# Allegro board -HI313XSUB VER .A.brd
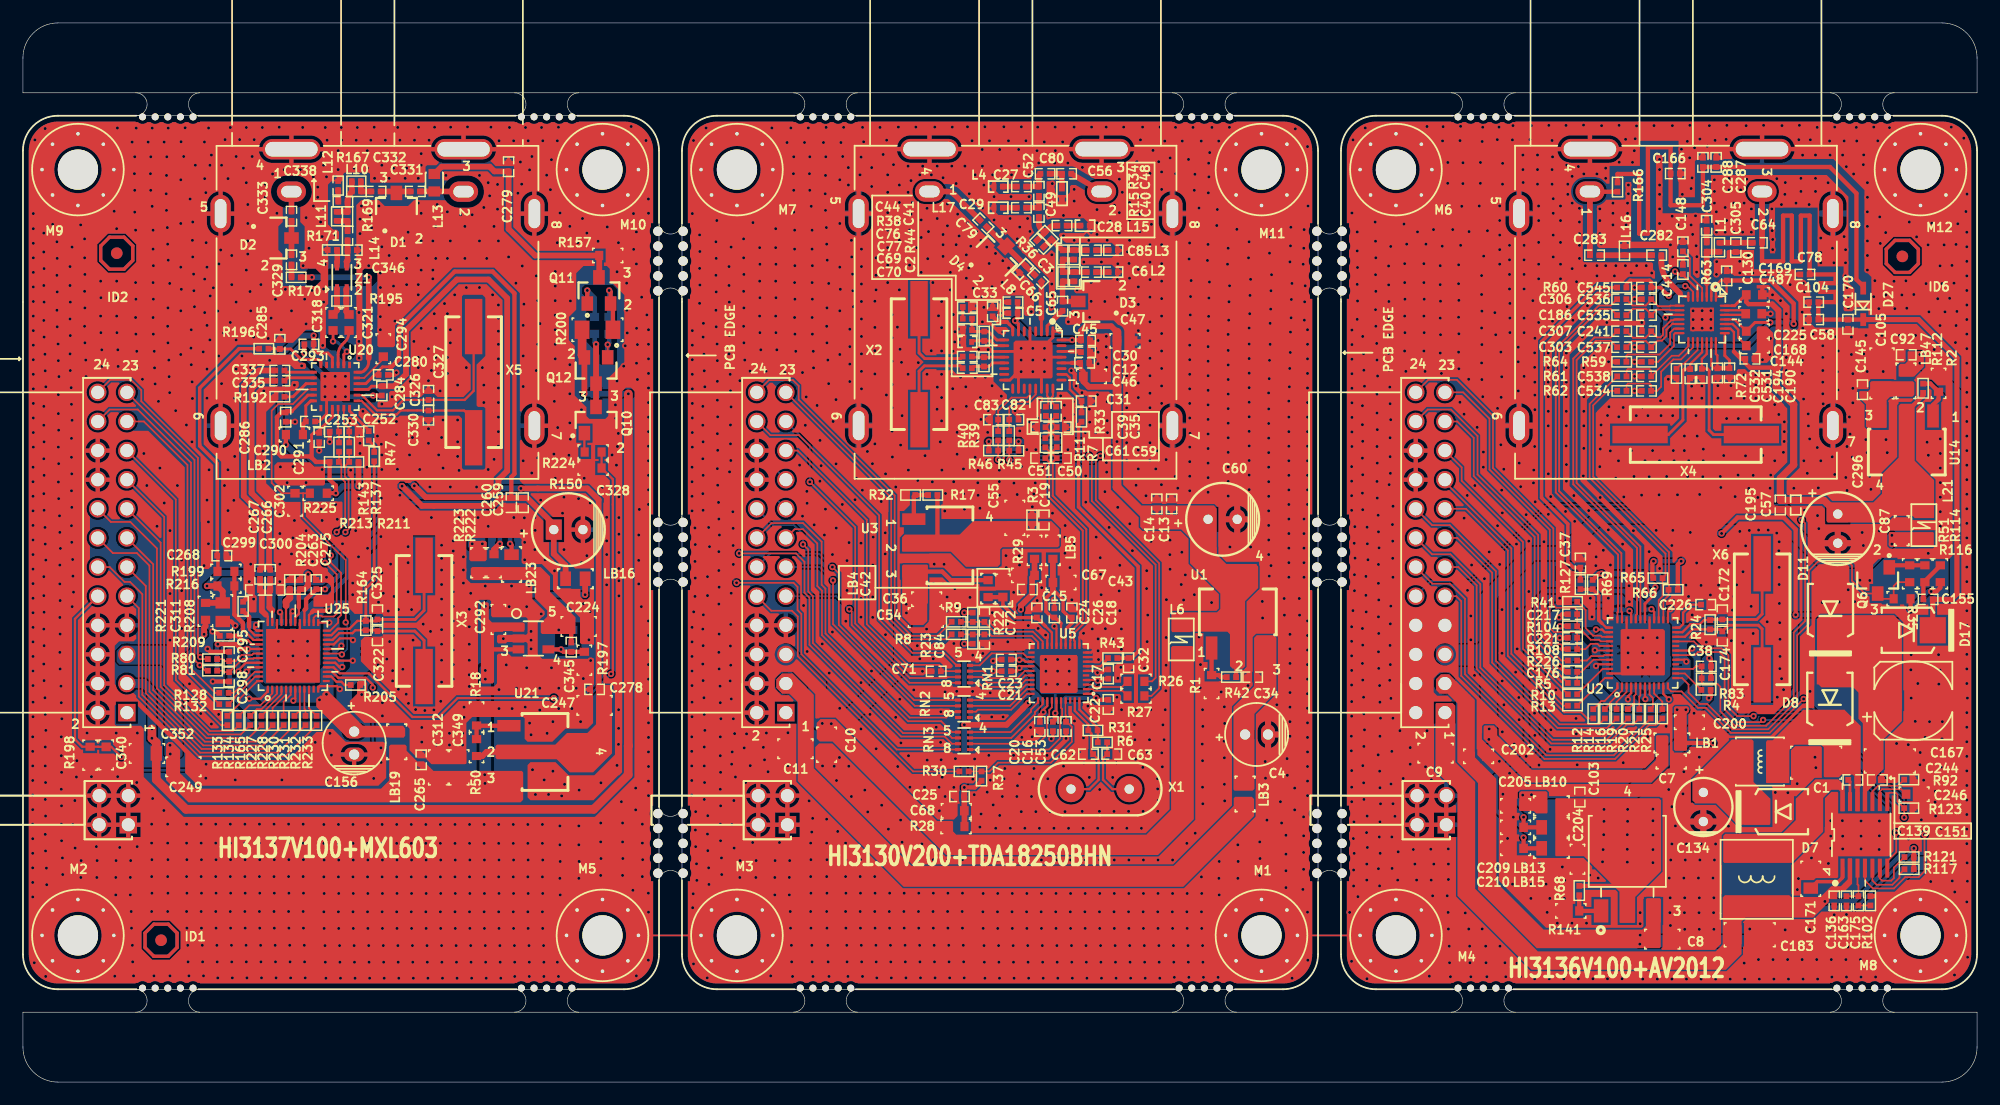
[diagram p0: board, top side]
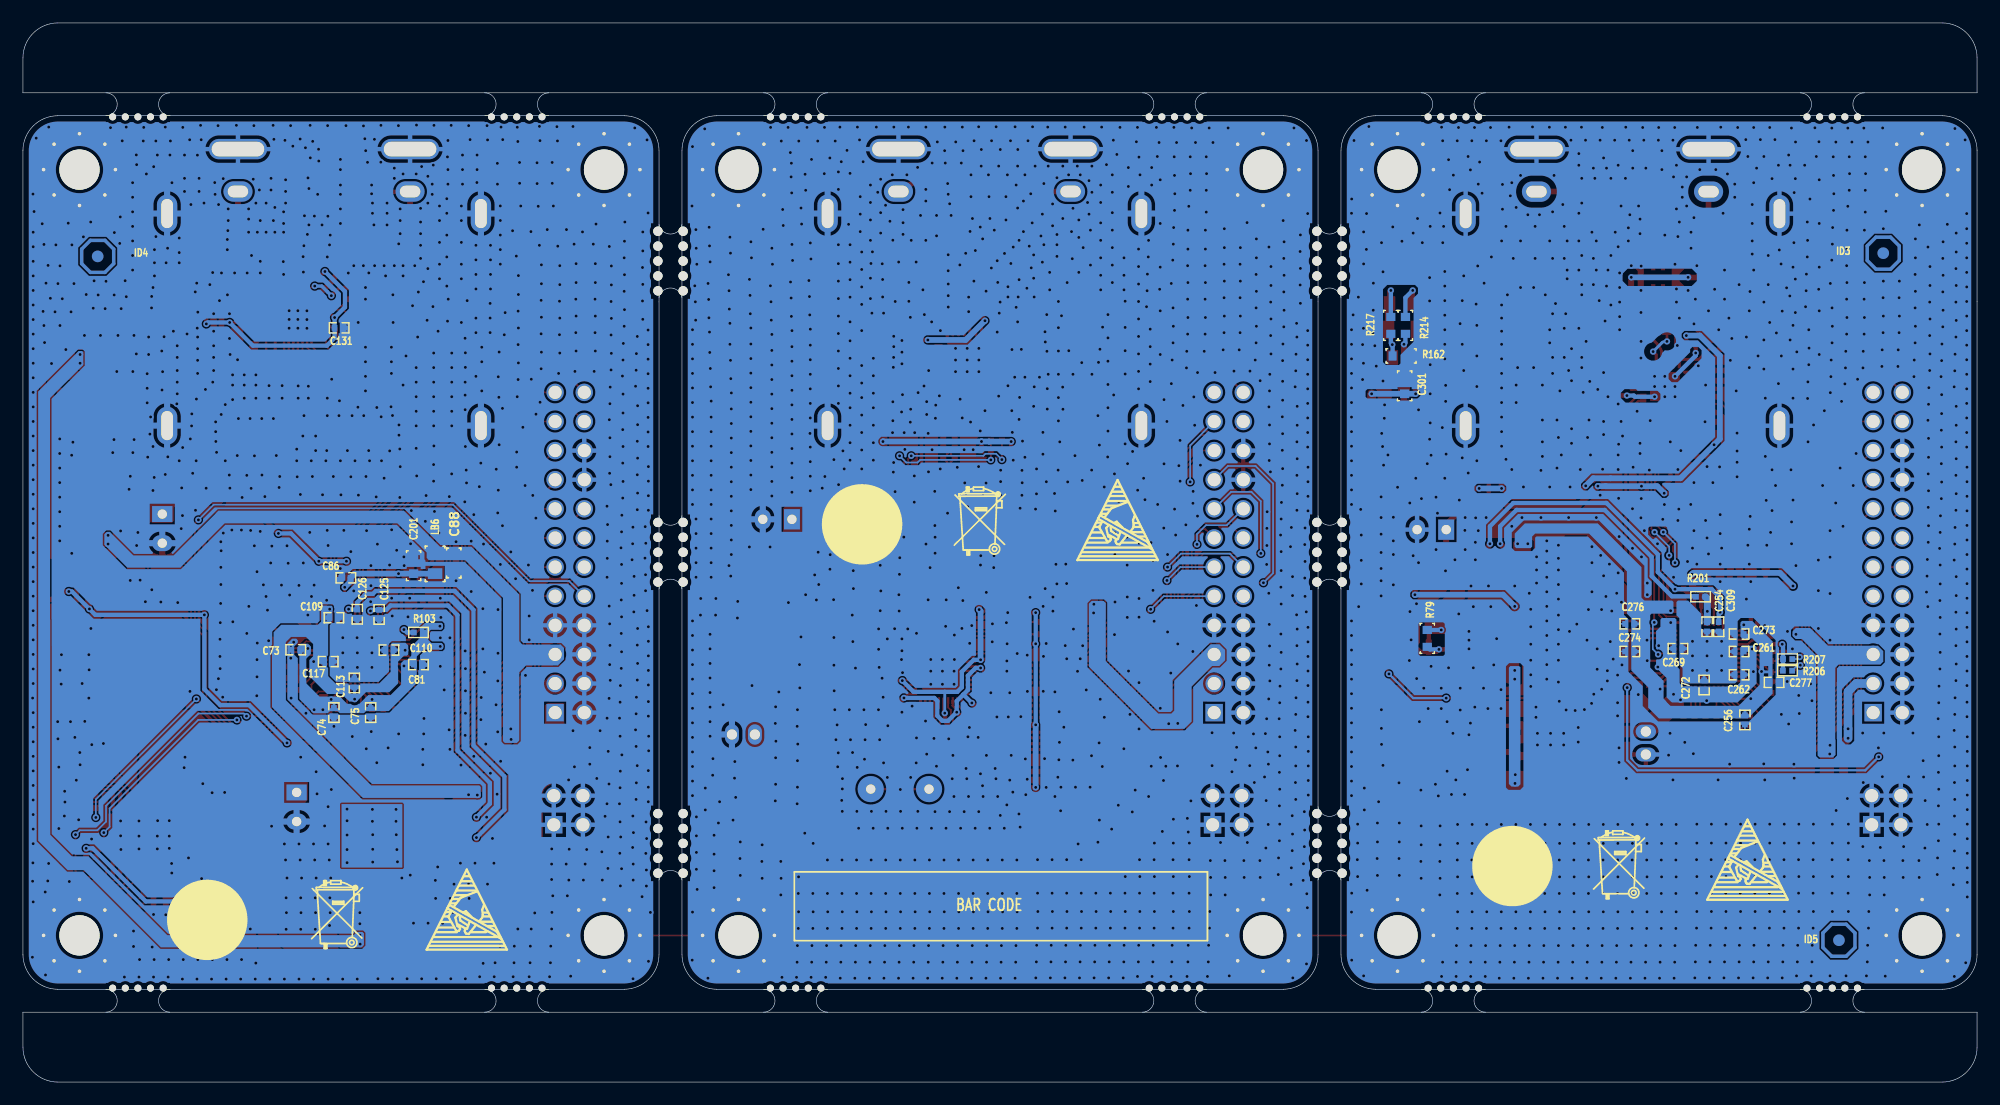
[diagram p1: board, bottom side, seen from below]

Outline 170.32 x 92.39 mm; copper layers: TOP, BOTTOM. Coordinates in mm from the lower left corner of the outline.
Outline path: 0,89.34 arc(0.89,91.5) 3.05,92.39 167.27,92.39 arc(169.43,91.5) 170.32,89.34 170.32,86.3 0,86.3 0,89.34 ; 0,81.25 arc(0.89,83.4) 3.05,84.3 52.39,84.3 arc(54.55,83.4) 55.44,81.25 55.44,11.14 arc(54.55,8.99) 52.39,8.1 3.05,8.1 arc(0.89,8.99) 0,11.14 0,81.25 ; 0,6.1 170.32,6.1 170.32,3.05 arc(169.43,0.89) 167.27,0 3.05,0 arc(0.89,0.89) 0,3.05 0,6.1 ; 57.44,81.25 arc(58.33,83.4) 60.49,84.3 109.83,84.3 arc(111.99,83.4) 112.88,81.25 112.88,11.14 arc(111.99,8.99) 109.83,8.1 60.49,8.1 arc(58.33,8.99) 57.44,11.14 57.44,81.25 ; 114.88,81.25 arc(115.77,83.4) 117.93,84.3 167.27,84.3 arc(169.43,83.4) 170.32,81.25 170.32,11.14 arc(169.43,8.99) 167.27,8.1 117.93,8.1 arc(115.77,8.99) 114.88,11.14 114.88,81.25

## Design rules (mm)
constraint set DEFAULT: min track width 0.152
net group 3V3_DVDD_C: nets 3V3_DVDD_C TS_RSTN_DEMO
net group $7N237: nets 1V2_DVDD_C $7N237
net group $8N351: nets $8N351 $8N354
net group $8N403: nets $8N403 $8N416
net group DIFFPAIR25: nets 3136_QOUT_N 3136_QOUT_P
net group DIFFPAIR26: nets 3136_IOUT_N 3136_IOUT_P
net group DIFFPAIR27: nets $8N249 $8N251
net group DIFFPAIR28: nets $8N253 $8N255
net group DIFFPAIR29: nets DEMO_VIN DEMO_VIP
net group DIFFPAIR30: nets $4N336 $4N337
net group DIFFPAIR31: nets $4N333 $4N334
net group 00: nets GND
net group $8N297: nets 3V3_C 18250B_SCL_T 18250B_SDA_T $8N297 $8N299

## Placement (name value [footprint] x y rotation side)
C1  4.7UF  [SC1210]  156.29 27.86 180 top
C2  5.6PF/NC  [SC0402]  83.76 62.83 270 top
C3  5.6PF/NC  [SC0402]  88.66 73.13 315 top
C4  100UF  [CAPC2-79-217]  106.52 30.32 0 top
C5  10NF  [HSC0402]  86.29 67.08 180 top
C6  1.8PF/NC  [SC0402]  93.12 70.66 0 top
C7  10UF  [SC0603]  143.66 27.96 0 top
C8  10UF  [SC0805]  142.88 12.46 0 top
C9  10UF  [SC0805]  123.12 28.7 180 top
C10  10UF  [SC0805]  70.05 29.43 270 top
C11  10UF  [SC0805]  67.33 29.08 180 top
C12  47NF  [SC0402]  92.54 62.74 0 top
C13  47NF  [SC0402]  100.12 50.44 90 top
C14  47NF  [SC0402]  98.82 50.44 90 top
C15  100NF  [SC0402]  87.55 42.97 180 top
C16  100NF  [SC0402]  89.77 31.02 270 top
C17  100NF  [SC0402]  94.6 35.59 90 top
C18  100NF  [SC0402]  91.42 40.92 90 top
C19  100NF  [SC0402]  88.99 49.04 90 top
C20  100NF  [SC0402]  88.63 31.02 270 top
C21  100NF  [SC0402]  85.71 35.84 180 top
C22  100NF  [SC0402]  94.6 32.94 270 top
C23  100NF  [SC0402]  85.71 36.86 180 top
C24  100NF  [SC0402]  88.37 40.92 90 top
C25  100NF  [SC0402]  81.63 24.91 180 top
C26  100NF  [SC0402]  89.9 40.92 90 top
C27  180PF  [SC0402]  87.03 78.12 180 top
C28  120PF  [SC0402]  90.56 74.71 0 top
C29  47PF  [SC0402]  87.03 76.27 180 top
C30  100NF  [SC0402]  92.62 63.67 180 top
C31  100NF  [SC0402]  92.67 59.41 0 top
C32  100NF  [SC0402]  96.36 36.58 270 top
C33  100NF  [SC0402]  86.29 68.04 180 top
C34  100NF  [SC0402]  107.18 35.32 180 top
C35  100NF  [SC0402]  90.05 58.52 270 top
C36  100NF  [SC0603]  78.77 42.12 0 top
C37  100NF  [SC0402]  135.75 45.28 90 top
C38  100NF  [SC0402]  146.72 36.26 0 top
C39  100NF  [SC0402]  89.16 58.52 270 top
C40  4.7PF/NC  [SC0402]  91.65 70.25 270 top
C41  100NF  [SC0402]  84.51 67.2 90 top
C42  1UF  [SC0603]  85.41 43.01 90 top
C43  1UF  [SC0603]  90.47 43.58 0 top
C44  220NF  [SC0402]  82.31 67.61 0 top
C45  470PF/NC  [SC0402]  92.62 64.7 0 top
C46  2.2UF  [SC0603]  93.12 61.56 0 top
C47  2.2UF  [SC0603]  96.06 64.66 0 top
C48  4.7PF/NC  [SC0402]  91.63 72.16 270 top
C49  22PF  [SC0402]  88.55 75.86 270 top
C50  18PF/NC  [SC0402]  90.51 54.43 0 top
C51  18PF/NC  [SC0402]  88.7 54.43 180 top
C52  18PF  [SC0402]  88.55 77.71 270 top
C53  1NF  [SC0402]  90.91 31.02 270 top
C54  10UF  [SC0805]  78.7 40.52 0 top
C55  10UF  [SC0805]  86.45 49.22 90 top
C56  1NF  [SC0402]  90.97 79.24 180 top
C57  10NF  [HSC0402]  154.52 50.34 270 top
C58  39PF/NC  [SC0402]  156.08 66.51 180 top
C59  6.8PF  [SC0402]  90.5 57.14 180 top
C60  220UF  [CAPC2-100-250]  104.56 49.09 0 top
C61  6.8PF  [SC0402]  88.72 57.13 180 top
C62  30PF  [SC0402]  92.87 28.61 180 top
C63  30PF  [SC0402]  94.9 28.61 0 top
C64  39PF  [SC0402]  151.17 73.21 180 top
C65  4.7NF  [SC0402]  90.61 67.69 270 top
C66  4.7NF  [SC0402]  88.48 70.12 315 top
C67  10UF  [SC0603]  87.47 44.2 180 top
C68  10UF  [SC0603]  81.35 23.67 180 top
C69  30PF  [SC0402]  82.3 63.29 180 top
C70  30PF  [SC0402]  82.3 62.28 180 top
C71  1PF/NC  [SC0402]  79.6 35.83 0 top
C72  100PF  [SC0402]  83.8 40.54 90 top
C73  100NF  [SC0402]  146.54 37.71 0 bottom
C74  100NF  [SC0402]  143.21 32.23 270 bottom
C75  100NF  [SC0402]  140.01 32.23 270 bottom
C76  2.7NF  [SC0402]  82.31 65.6 180 top
C77  6.8N  [HSC0402-TA]  82.32 64.56 180 top
C78  39PF/NC  [SC0402]  155.32 70.45 180 top
C79  4.7NF  [SC0402]  83.71 74.9 315 top
C80  33PF  [SC0402]  89.09 79.24 180 top
C81  100NF  [SC0402]  135.85 36.42 180 bottom
C82  10PF  [SC0402]  86.37 57.79 0 top
C83  10PF  [SC0402]  84.59 57.78 180 top
C84  100PF  [SC0402]  83.8 38.64 270 top
C85  1.5PF/NC  [SC0402]  93.12 72.56 0 top
C86  100NF  [SC0402]  142.17 43.99 0 bottom
C87  10UF  [SC0603]  163.75 48.1 90 top
C88  10UF  [SC0603]  132.77 45.28 270 bottom
C92  100NF  [SC0402]  164.14 63.44 180 top
C103  100NF  [SC0402]  135.7 24.86 90 top
C104  39PF  [SC0402]  156.08 68.04 180 top
C105  10UF  [SC1206]  162.03 61.82 90 top
C109  100NF  [SC0402]  143.21 40.51 180 bottom
C110  100NF  [SC0402]  138.41 37.69 0 bottom
C113  100NF  [SC0402]  141.44 34.82 90 bottom
C117  100NF  [SC0402]  143.71 36.68 180 bottom
C125  100NF  [SC0402]  139.28 40.79 270 bottom
C126  100NF  [SC0402]  141.18 40.81 270 bottom
C130  1NF  [SC0402]  148.5 70.33 90 top
C131  100NF  [SC0402]  142.76 65.79 180 bottom
C134  22UF  [CAPC2-100-200]  146.46 24 270 top
C136  100NF  [SC0402]  157.87 15.81 270 top
C139  100NF  [SC0402]  159.49 26.36 0 top
C144  100NF  [SC0402]  150.52 63.09 0 top
C145  100NF  [SC0402]  160.33 60.39 90 top
C148  22PF  [SC0402]  144.68 72.87 90 top
C151  100NF  [SC0402]  161.63 26.36 0 top
C155  100NF  [SC0402]  166.05 42.11 0 top
C156  100UF  [CAPC2-79-217]  28.87 30.57 270 top
C163  470PF  [SC0402]  158.94 15.81 90 top
C166  1NF  [SC0402]  144.01 79.25 0 top
C167  47UF/NC  [SCAPC2-0606]  164.76 33.27 0 top
C168  1NF  [SC0603]  150.9 64.23 180 top
C169  1NF/NC  [SC0603]  150.9 68.67 180 top
C170  1NF  [SC0402]  159.06 66.11 270 top
C171  220NF  [SC0805]  155.82 17.73 270 top
C172  30PF  [SC0402]  148.12 40.76 90 top
C174  30PF  [SC0402]  148.12 38.91 270 top
C175  47NF  [SC0402]  159.98 15.81 90 top
C176  1PF/NC  [SC0402]  135.06 35.78 180 top
C183  10UF  [SC1206]  150.5 12.85 0 top
C186  100NF  [SC0402]  139.35 66.9 180 top
C190  100NF/NC  [SC0402]  148.74 61.86 270 top
C194  100NF  [SC0402]  147.69 61.86 270 top
C195  100NF  [SC0402]  153.17 50.34 90 top
C200  10UF  [SC0603]  145.25 31.39 0 top
C201  10UF  [SC0603]  136.27 45.05 90 bottom
C202  10UF  [SC0603]  126.87 28.42 0 top
C204  10UF  [SC0603]  135.49 19.44 270 top
C205  10UF  [SC0603]  130.09 24.1 180 top
C209  10UF  [SC0603]  130.09 22.22 180 top
C210  10UF  [SC0603]  130.09 20.39 180 top
C217  33PF/NC  [SC0402]  135.06 40.81 180 top
C221  33PF/NC  [SC0402]  135.06 38.75 180 top
C224  10UF  [SC0805]  48.44 39.74 0 top
C225  1NF/NC  [SC0603]  150.9 65.5 180 top
C226  10PF  [SC0402]  146.67 41.65 0 top
C241  33PF  [SC0402]  141.51 65.5 180 top
C244  1UF/NC  [SC1206]  162.72 28.01 0 top
C246  22NF  [SC0603]  164.83 25.11 0 top
C247  10UF  [SC0805]  49.82 32.86 180 top
C249  10UF  [SC0805]  13.98 27.5 0 top
C252  47PF  [SC0402]  28.84 56.74 0 top
C253  47PF  [SC0402]  27.14 56.74 180 top
C254  100NF  [SC0402]  23.53 39.72 270 bottom
C256  100NF  [SC0402]  20.23 31.59 270 bottom
C259  100NF  [SC0402]  43.6 50.54 270 top
C260  100NF  [SC0402]  42.57 50.54 270 top
C261  100NF  [SC0402]  20.74 37.56 0 bottom
C262  100NF  [SC0402]  20.74 35.53 0 bottom
C263  100NF/NC  [SC0402]  24.14 43.4 90 top
C265  100NF  [SC0402]  34.71 28.11 90 top
C266  100NF  [SC0402]  21.55 44.29 90 top
C267  100NF  [SC0402]  20.66 44.29 90 top
C268  100NF  [SC0402]  17.34 45.92 0 top
C269  100NF  [SC0402]  26.07 37.81 180 bottom
C272  100NF  [SC0402]  23.79 34.64 90 bottom
C273  100NF  [SC0402]  20.74 39.08 0 bottom
C274  100NF  [SC0402]  30.27 37.56 0 bottom
C275  100NF  [SC0402]  25.57 43.4 90 top
C276  100NF  [SC0402]  30.27 39.97 0 bottom
C277  100NF/NC  [SC0402]  17.69 34.87 180 bottom
C278  100NF/NC  [SC0402]  49.82 34.26 180 top
C279  100NF  [SC0402]  42.33 79.85 90 top
C280  100NF  [SC0402]  31.41 61.69 180 top
C282  47PF  [SC0402]  142.39 72.13 0 top
C283  47PF  [SC0402]  136.98 72.13 0 top
C284  100NF  [SC0402]  31.28 60.29 90 top
C285  100NF  [SC0402]  22.39 64.36 90 top
C286  100NF  [SC0402]  22.9 58.01 270 top
C287  2.2NF  [SC0402]  147.58 80.23 90 top
C288  1NF  [SC0402]  146.43 80.23 90 top
C290  100NF  [SC0402]  25.06 57.63 0 top
C291  100NF  [SC0402]  25.82 56.23 270 top
C292  2.2UF  [SC0603]  41.44 40.35 90 top
C293  10NF  [SC0402]  24.93 64.36 0 top
C294  560PF  [SC0603]  31.41 63.98 270 top
C295  22PF  [SC0402]  17.97 37.13 90 top
C296  220UF  [CAPC2-100-250]  158.17 48.28 270 top
C298  22PF  [SC0402]  17.97 35.35 270 top
C299  22PF/NC  [SC0402]  20.26 42.92 180 top
C300  22PF/NC  [SC0402]  21.96 42.92 0 top
C301  1UF  [SC0603]  49.89 60.74 90 bottom
C302  1UF  [SC0603]  23.71 50.67 270 top
C303  100NF  [SC0402]  139.35 64.1 180 top
C304  100NF/NC  [SC0402]  146.75 74.74 270 top
C305  100NF/NC  [SC0402]  149.29 72.81 90 top
C306  100NF  [SC0402]  139.35 68.29 180 top
C307  100NF  [SC0402]  139.35 65.5 180 top
C309  1NF  [SC0402]  22.52 39.72 270 bottom
C311  2.2UF  [SC0805]  17.41 40.99 270 top
C312  2.2UF  [SC0805]  36.21 27.45 90 top
C318  1NF  [SC0603]  27.03 66.26 270 top
C321  1NF  [SC0603]  28.42 66.26 270 top
C322  30PF  [SC0402]  30.9 38.93 90 top
C325  30PF  [SC0402]  30.9 40.76 270 top
C326  30PF/NC  [SC0402]  35.35 58.17 270 top
C327  30PF/NC  [SC0402]  35.35 59.91 90 top
C328  220UF  [CAPC2-100-250]  47.54 48.19 0 top
C329  4.7NF  [SC0402]  23.41 71.72 270 top
C330  4.7NF  [SC0402]  30.14 56.38 270 top
C331  4.7NF  [SC0402]  34.2 77.69 180 top
C332  4.7NF  [SC0402]  30.77 77.69 180 top
C333  4.7NF  [SC0402]  23.41 75.53 270 top
C335  4.7NF  [SC0402]  22.39 61.18 180 top
C337  4.7NF  [SC0402]  22.39 62.07 180 top
C338  33PF/NC  [SC0402]  27.89 76.8 180 top
C340  4.7UF  [SC0603]  7.25 28.54 270 top
C345  10PF  [SC0402]  47.79 37.94 270 top
C346  2.7PF  [SC0402]  28.7 72.57 180 top
C349  10UF  [SC0805]  38.01 27.45 90 top
C352  10UF  [SC0805]  10.81 28.67 180 top
C414  10NF  [SC0402]  144.68 70.88 90 top
C487  1UF  [SC0603]  150.85 67.02 180 top
C531  27PF  [SC0402]  146.33 61.82 270 top
C532  27PF  [SC0402]  145.32 61.79 270 top
C534  10PF  [SC0402]  141.51 60.29 180 top
C535  33PF  [SC0402]  141.51 66.9 180 top
C536  33PF  [SC0402]  141.51 68.29 180 top
C537  33PF  [SC0402]  141.51 64.1 180 top
C538  10PF  [SC0402]  141.51 61.56 180 top
C545  100PF  [SC0402]  141.51 69.31 180 top
D1  D2-3_A  [SOT23]  32.55 76.42 0 top
D2  D2-3_A  [SOT23]  22.26 73.63 270 top
D3  D2-3_A  [SOT23]  93.12 68.09 90 top
D4  D2-3_A  [SOT23]  84.89 72.1 315 top
D7  DIODE  [SD1714A]  153.42 23.59 180 top
D8  DIODE  [SD1714A]  157.49 33.55 270 top
D11  DIODE  [SD1714A]  157.54 41.29 270 top
D17  DIODE  [SD1714A]  164.17 39.41 0 top
D27  D_A  [HSOD323A]  160.4 67.89 270 top
ID1  -  [ID-BOARD]  12.04 12.37 0 top
ID2  -  [ID-BOARD]  8.18 72.31 0 top
ID3  -  [ID-BOARD]  8.18 72.31 180 bottom
ID4  -  [ID-BOARD]  163.8 72.03 180 bottom
ID5  -  [ID-BOARD]  12.04 12.37 180 bottom
ID6  -  [ID-BOARD]  163.8 72.03 0 top
J1  -  [JTDA18250]  86.51 66.52 270 top
J2  -  [JTDA18250]  30.9 66.5 270 top
J3  D2008_2X12A  [HEAD0212-RM-SUB]  122.66 46.2 270 top
J4  D2008_2X12A  [HEAD0212-RM-SUB]  7.79 46.2 270 top
J5  1204_041_12_1  [HEAD0202-RM]  122.78 23.72 270 top
J6  1204_041_12_1  [HEAD0202-RM]  65.36 23.72 270 top
J7  D2008_2X12A  [HEAD0212-RM-SUB]  65.23 46.2 270 top
J15  1204_041_12_1  [HEAD0202-RM]  7.91 23.72 270 top
J16  -  [JTDA18250]  144.08 66.52 270 top
L1  3.3NH  [SL0402]  147.87 72.82 270 top
L2  2.2NH/NC  [SL0402]  95.03 70.66 0 top
L3  2.2NH/NC  [SL0402]  95.03 72.56 0 top
L4  82N  [HSL0402-TC]  85.01 78.12 180 top
L5  150N  [HSL0402]  90.56 77.5 270 top
L6  4.7UH/NC  [HSL1007]  100.96 38.61 90 top
L7  22UH/2A  [L6X6X4_5]  151.11 17.69 90 top
L8  82N/NC  [HSL0402-TC]  87.14 70.91 225 top
L9  1UH  [SWPA4020S]  151.39 27.96 0 top
L10  68NH/NC  [SL0402]  29.06 78.58 180 top
L11  68NH/NC  [SL0402]  27.34 75.52 270 top
L12  82NH/NC  [SL0402]  27.47 78.2 90 top
L13  270NH  [SL0603A]  35.85 78.45 90 top
L14  3.3NH  [SL0402]  28.3 73.83 270 top
L15  100N  [HSL0402-TC]  92.57 74.71 0 top
L16  NC/3.3NH  [SL0402]  139.59 72.52 270 top
L17  100N  [HSL0402-TC]  85.01 76.27 180 top
L21  4.7UH/NC  [HSL1007]  165.68 48.58 90 top
LB1  MGLB2012_220T_LF  [SL0805]  143.72 29.58 0 top
LB2  MGLB1608_030T_LF  [SL0603]  23.66 56.48 180 top
LB3  220OHM  [SL0805]  106.52 25.13 270 top
LB4  MGLB1608_030T_LF  [SL0603]  84.12 43.04 270 top
LB5  MGLB1608_030T_LF  [SL0603]  89.77 46.39 90 top
LB6  MGLB2012_220T_LF  [SL0805]  134.4 45.21 270 bottom
LB10  MGLB2012_220T_LF  [SL0805]  133.22 24.1 180 top
LB13  MGLB2012_220T_LF  [SL0805]  133.22 22.22 180 top
LB15  MGLB2012_220T_LF  [SL0805]  133.22 20.39 180 top
LB16  MGLB2012_220T_LF  [SL0805]  48.15 43.91 180 top
LB19  MGLB2012_220T_LF  [SL0805]  32.58 29.69 90 top
LB23  MGLB2012_220T_LF  [SL0805]  42.58 45.15 90 top
LB47  MGLB2012_220T_LF  [SL0805]  164.12 61.17 270 top
M1  138MIL_STAR_HOLE_APPLY_TO_M3  [HOLE138-8STAR]  107.95 12.79 0 top
M2  138MIL_STAR_HOLE_APPLY_TO_M3  [HOLE138-8STAR]  4.79 12.79 0 top
M3  138MIL_STAR_HOLE_APPLY_TO_M3  [HOLE138-8STAR]  62.23 12.79 0 top
M4  138MIL_STAR_HOLE_APPLY_TO_M3  [HOLE138-8STAR]  119.67 12.79 0 top
M5  138MIL_STAR_HOLE_APPLY_TO_M3  [HOLE138-8STAR]  50.51 12.79 0 top
M6  138MIL_STAR_HOLE_APPLY_TO_M3  [HOLE138-8STAR]  119.67 79.6 0 top
M7  138MIL_STAR_HOLE_APPLY_TO_M3  [HOLE138-8STAR]  62.23 79.6 0 top
M8  138MIL_STAR_HOLE_APPLY_TO_M3  [HOLE138-8STAR]  165.39 12.79 0 top
M9  138MIL_STAR_HOLE_APPLY_TO_M3  [HOLE138-8STAR]  4.79 79.6 0 top
M10  138MIL_STAR_HOLE_APPLY_TO_M3  [HOLE138-8STAR]  50.51 79.6 0 top
M11  138MIL_STAR_HOLE_APPLY_TO_M3  [HOLE138-8STAR]  107.95 79.6 0 top
M12  138MIL_STAR_HOLE_APPLY_TO_M3  [HOLE138-8STAR]  165.39 79.6 0 top
NOREF  -  [unnamed]  56.44 71.62 90 top
NOREF#2  -  [unnamed#2]  160.3 7.1 0 top
NOREF#3  -  [#3]  5.71 164.56 0 top
NOREF#4  -  [unnamed]  56.44 46.22 90 top
NOREF#5  -  [unnamed]  113.88 71.62 90 top
NOREF#6  -  [unnamed]  113.88 46.22 90 top
NOREF#7  -  [#3]  -117.91 -114.28 0 top
NOREF#8  -  [unnamed#2]  12.62 7.1 0 top
NOREF#9  -  [unnamed#2]  102.97 85.3 180 top
NOREF#10  -  [unnamed#2]  160.3 85.3 180 top
NOREF#11  -  [unnamed#2]  45.64 85.3 180 top
NOREF#12  -  [unnamed]  113.88 20.82 90 top
NOREF#13  -  [unnamed#2]  45.64 7.1 0 top
NOREF#14  -  [#3]  16.38 219.98 0 top
NOREF#15  -  [unnamed]  56.44 20.82 90 top
NOREF#16  -  [unnamed#2]  127.28 85.3 180 top
NOREF#17  -  [unnamed#2]  69.95 7.1 0 top
NOREF#18  -  [unnamed#2]  69.95 85.3 180 top
NOREF#19  -  [#3]  103.43 155.52 0 top
NOREF#20  -  [unnamed#2]  102.97 7.1 0 top
NOREF#21  -  [unnamed#2]  127.28 7.1 0 top
NOREF#22  -  [unnamed#2]  12.62 85.3 180 top
NOREF#23  -  [#3]  153.75 14.37 180 bottom
NOREF#24  -  [#3]  84.38 49.06 180 bottom
NOREF#25  -  [#3]  20.7 18.91 180 bottom
NOREF#26  -  [#3]  75.6 48.53 180 bottom
NOREF#27  -  [#3]  140.4 14.73 180 bottom
NOREF#28  -  [#3]  39.99 19.07 180 bottom
NOREF#29  -  [#3]  85.08 15.34 180 bottom
NOREF#30  -  [#3]  96.67 48.88 180 bottom
NOREF#31  -  [#3]  132.32 14.55 180 bottom
NOREF#32  -  [#3]  28.66 19.07 180 bottom
Q6  NPN-BEC  [SOT23]  161.65 43.76 180 top
Q10  NPN-BEC  [SOT23]  49.95 57.75 0 top
Q11  MMBT4403LT1  [SOT23]  50.2 69.06 0 top
Q12  MMBT4403LT1  [SOT23]  49.95 62.07 180 top
R1  249  [SR0603]  103.6 34.77 270 top
R2  249  [SR0603]  166.96 60.95 90 top
R3  100/NC  [SR0402]  87.95 49.04 90 top
R4  2K  [SR0402]  146.69 34.21 0 top
R5  33  [SR0402]  135.06 34.82 0 top
R6  100  [SR0402]  94.09 29.64 0 top
R7  100  [SR0402]  90.1 55.8 270 top
R8  33  [SR0402]  81.35 39.06 0 top
R9  33  [SR0402]  81.35 40.15 0 top
R10  33  [SR0402]  135.06 33.83 0 top
R11  100  [SR0402]  89.11 55.77 270 top
R12  33  [SR0402]  136.86 32.12 90 top
R13  33  [SR0402]  135.06 32.84 0 top
R14  33  [SR0402]  137.88 32.12 90 top
R15  0  [SR0402]  90.65 70.25 270 top
R16  33  [SR0402]  138.9 32.12 90 top
R17  237/NC  [SR0402]  79.3 51.21 0 top
R18  110  [SR0603]  39.54 31.84 90 top
R19  33  [SR0402]  139.89 32.12 90 top
R20  33  [SR0402]  140.88 32.12 90 top
R21  33  [SR0402]  141.87 32.12 90 top
R22  2K  [SR0402]  82.79 40.54 270 top
R23  2K  [SR0402]  82.79 38.64 90 top
R24  1MEG  [SR0402]  147.05 39.9 270 top
R25  33  [SR0402]  142.88 32.12 90 top
R26  0  [SR0603]  97.01 34.96 0 top
R27  0  [SR0603]  97.01 33.69 0 top
R28  0  [SR0603]  81.32 22.29 0 top
R29  0  [SR0603]  88.17 46.38 270 top
R30  33  [SR0402]  82.02 27.1 0 top
R31  1MEG  [SR0402]  93.26 30.68 0 top
R32  0  [SR0402]  77.37 51.21 180 top
R33  0  [SR0402]  92.26 58.01 270 top
R34  0  [SR0402]  90.63 72.16 270 top
R35  150K  [SR0603]  167.11 44.34 90 top
R36  0  [SR0402]  89.35 73.82 315 top
R37  10K  [SR0402]  83.55 26.69 90 top
R38  430  [SR0402]  82.31 66.59 180 top
R39  47  [SR0402]  85.96 56.38 270 top
R40  47  [SR0402]  85 56.38 270 top
R41  2K  [SR0402]  135.06 41.9 180 top
R42  150  [SR0402]  105.33 35.32 0 top
R43  4.7K  [SR0402]  94.98 36.99 180 top
R44  390/NC  [SR0402]  83.79 65.07 270 top
R45  2K  [SR0402]  86.37 55.07 0 top
R46  2K  [SR0402]  84.59 55.09 180 top
R47  0/NC  [SR0402]  30.62 54.56 90 top
R50  249  [SR0603]  39.54 29.18 270 top
R51  19.6K  [SR0603]  164.45 44.34 90 top
R59  2K/NC  [SR0402]  141.51 62.83 180 top
R60  220  [SR0402]  139.35 69.31 0 top
R61  0  [SR0402]  139.36 61.56 180 top
R62  0  [SR0402]  139.36 60.29 180 top
R63  0/NC  [SR0402]  146.76 72.84 90 top
R64  0  [SR0402]  139.35 62.83 180 top
R65  2K  [SR0402]  142.5 43.96 0 top
R66  2K  [SR0402]  143.83 42.94 180 top
R68  150/NC  [SR0402]  135.64 16.71 90 top
R69  1K  [SR0402]  136.81 43.4 270 top
R72  2K/NC  [SR0402]  144.12 61.82 270 top
R79  82.5K  [SR0603]  47.92 38.7 270 bottom
R80  33  [SR0402]  16.52 36.9 0 top
R81  33  [SR0402]  16.52 35.88 0 top
R83  10K  [SR0402]  146.72 35.22 0 top
R92  10K  [SR0402]  164.37 26.38 0 top
R102  4.7K  [SR0402]  161.02 15.81 270 top
R103  2K  [SR0402]  135.84 39.22 180 bottom
R104  2K  [SR0402]  135.06 39.77 0 top
R108  2K  [SR0402]  135.06 37.76 0 top
R112  150  [SR0402]  165.62 60.52 270 top
R114  2K  [SR0603]  165.77 44.34 270 top
R116  2K  [SR0603]  163.79 42.16 0 top
R117  75K  [SR0402]  164.4 18.56 180 top
R121  75K  [SR0402]  164.4 19.63 180 top
R123  75K  [SR0402]  164.37 23.89 0 top
R127  4.7K  [SR0402]  135.75 43.4 90 top
R128  33  [SR0402]  17.51 33.95 0 top
R132  33  [SR0402]  17.51 32.96 0 top
R133  33  [SR0402]  17.82 31.54 90 top
R134  33  [SR0402]  18.81 31.54 90 top
R137  33  [SR0402]  28.44 55.39 270 top
R141  0  [SR0603]  134.91 14.93 180 top
R143  33  [SR0402]  27.55 55.39 270 top
R150  10K  [SR0603]  49.7 53.56 0 top
R157  10K/NC  [SR0603]  50.97 72.1 180 top
R162  10K  [SR0603]  50.2 63.34 0 bottom
R164  1MEG  [SR0402]  29.88 39.82 90 top
R165  33  [SR0402]  19.8 31.54 90 top
R166  NC/0  [SR0402]  138.98 78.07 90 top
R167  0  [SR0402]  29.07 77.69 180 top
R169  0  [SR0402]  28.3 75.51 270 top
R170  0  [SR0402]  23.81 70.2 0 top
R171  0  [SR0402]  26.96 72.59 180 top
R192  0  [SR0402]  22.39 59.78 180 top
R195  1K/NC  [SR0402]  27.78 68.14 180 top
R196  1K  [SR0402]  20.99 63.98 0 top
R197  220K  [SR0603]  48.93 36.8 270 top
R198  4.7K  [SR0603]  5.86 28.52 270 top
R199  4.7K  [SR0603]  17.69 44.54 180 top
R200  2.7  [SR1206]  50.08 65.63 0 top
R201  22  [SR0402]  24.09 42.34 180 bottom
R204  22  [SR0402]  23.25 43.4 90 top
R205  2K  [SR0402]  28.97 34.64 0 top
R206  2K  [SR0402]  16.52 35.88 180 bottom
R207  2K  [SR0402]  16.51 36.9 180 bottom
R208  2K  [SR0402]  19.19 41.5 90 top
R209  2K  [SR0402]  17.57 38.93 180 top
R211  2K  [SR0402]  28.84 54.1 180 top
R213  2K  [SR0402]  27.13 54.1 0 top
R214  1.5K  [SR0603]  49.82 66.01 90 bottom
R216  1K  [SR0603]  17.69 43.27 0 top
R217  1K  [SR0603]  51.09 66.01 90 bottom
R221  0  [SR0603]  15.91 41.07 90 top
R222  0  [SR0603]  41.06 45.31 90 top
R223  0  [SR0603]  39.66 45.31 90 top
R224  470  [SR0603]  49.7 54.96 0 top
R225  510K  [SR0603]  25.74 51.36 180 top
R226  33  [SR0402]  135.06 36.77 0 top
R227  33  [SR0402]  20.79 31.54 90 top
R228  33  [SR0402]  21.76 31.54 90 top
R230  33  [SR0402]  22.72 31.54 90 top
R231  33  [SR0402]  23.66 31.54 90 top
R232  33  [SR0402]  24.63 31.54 90 top
R233  33  [SR0402]  25.59 31.54 90 top
RN1  75  [SRN8-0804]  82.02 35.59 90 top
RN2  75  [SRN8-0804]  82.02 32.56 90 top
RN3  75  [SRN8-0804]  82.02 29.77 90 top
U1  AZ1117  [SOT223A]  105.89 41.01 0 top
U2  HI3136V100  [MLF48B-040-0606L]  141.17 37.44 0 top
U3  AZ1117H_ADJTRG1  [SOT223A]  80.8 46.82 270 top
U4  TDA18250BHN  [HVQFN32]  88.02 62.99 180 top
U5  HI3130V200  [MLF40B-040-0505L]  90.28 35.67 90 top
U12  AZ1117-ADJ  [TO-252]  139.83 18.3 0 top
U14  LM1117-ADJ  [SOT223A]  164.19 54.96 180 top
U17  MP8126  [TSSOP16EP]  160.22 21.56 0 top
U18  ETA5050S2F  [SOT23-5]  44.49 38.69 270 top
U20  MXL603  [MLF24B-050-0404L]  27.22 60.67 180 top
U21  AZ1117H_ADJTRG1  [SOT223A]  45.51 28.8 270 top
U25  HI3137V100_B  [MLF48G-040-0606L]  23.53 37.18 0 top
U34  AV2012  [QFN28B-040-0404LH]  146.36 66.53 180 top
X1  28.8MHZ  [XTAL2-200A]  93.89 25.56 180 top
X2  16MHZ  [SX2-1205]  78.1 62.63 270 top
X3  24MHZ  [SX2-1205]  34.96 40.23 90 top
X4  27MHZ  [SX2-1205]  145.8 56.48 0 top
X5  24MHZ  [SX2-1205]  39.28 61.05 270 top
X6  24MHZ  [SX2-1205]  151.59 40.36 90 top
Z1  ATB2012E_75011M_T000  [RF4-TDK-ATB2012E]  27.8 70.2 90 top

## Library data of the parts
C1 = SC1210
C2 C3 C6 C12-C35 C37-C41 C44 C45 C48-C53 C56 C58 C59 C61-C66 C69-C76 C78-C86 C92 C103 C104 C109 C110 C113 C117 C125 C126 C130 C131 C136 C139 C144 C145 C148 C151 C155 C163 C166 C170 C172 C174-C176 C186 C190 C194 C195 C217 C221 C226 C241 C252-C254 C256 C259-C263 C265-C269 C272-C280 C282-C288 C290 C291 C293 C295 C298-C300 C303-C307 C309 C322 C325-C327 C329-C333 C335 C337 C338 C345 C346 C414 C531 C532 C534-C538 C545 = SC0402
C4 C156 = CAPC2-79-217
C5 C57 = HSC0402
C7 C36 C42 C43 C46 C47 C67 C68 C87 C88 C168 C169 C200-C202 C204 C205 C209 C210 C225 C246 C292 C294 C301 C302 C318 C321 C340 C487 = SC0603
C8-C11 C54 C55 C171 C224 C247 C249 C311 C312 C349 C352 = SC0805
C60 C296 C328 = CAPC2-100-250
C77 = HSC0402-TA: signal model: SC0402
C105 C183 C244 = SC1206
C134 = CAPC2-100-200
C167 = SCAPC2-0606
D1-D4 Q6 Q10-Q12 = SOT23
D7 D8 D11 D17 = SD1714A
D27 = HSOD323A
ID1-ID6 = ID-BOARD
J1 J2 J16 = JTDA18250
J3 J4 J7 = HEAD0212-RM-SUB
J5 J6 J15 = HEAD0202-RM
L1-L3 L10-L12 L14 L16 = SL0402
L4 L8 L15 L17 = HSL0402-TC
L5 = HSL0402
L6 L21 = HSL1007
L7 = L6X6X4_5
L9 = SWPA4020S
L13 = SL0603A
LB1 LB3 LB6 LB10 LB13 LB15 LB16 LB19 LB23 LB47 = SL0805
LB2 LB4 LB5 = SL0603
M1-M12 = HOLE138-8STAR
R1 R2 R18 R26-R28 R35 R50 R51 R79 R114 R116 R141 R150 R157 R162 R197-R199 R214 R216 R217 R221-R225 = SR0603
R3-R17 R19-R25 R30-R34 R39-R44 R47 R59-R66 R68 R69 R72 R80 R81 R83 R92 R102-R104 R108 R112 R117 R121 R123 R127 R128 R132-R134 R137 R143 R164-R167 R169-R171 R192 R195 R196 R201 R204-R209 R211 R213 R226-R228 R230-R233 = SR0402
R29 = SR0603: signal model: SR0402_75
R36-R38 R45 R46 = SR0402: signal model: SR0402_33
R200 = SR1206
RN1-RN3 = SRN8-0804
U1 U3 U14 U21 = SOT223A
U2 = MLF48B-040-0606L
U4 = HVQFN32
U5 = MLF40B-040-0505L
U12 = TO-252
U17 = TSSOP16EP
U18 = SOT23-5
U20 = MLF24B-050-0404L
U25 = MLF48G-040-0606L
U34 = QFN28B-040-0404LH
X1 = XTAL2-200A
X2-X6 = SX2-1205
Z1 = RF4-TDK-ATB2012E

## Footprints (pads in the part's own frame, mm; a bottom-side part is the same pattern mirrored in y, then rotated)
CAPC2-79-217
  oval 1.219x1.778 hole 0.889: 1(0,0) 2(2,0)
CAPC2-100-200
  rect 1.397x1.778 hole 0.813: 1(-1.27,0)
  oval 1.397x1.778 hole 0.813: 2(1.27,0)
CAPC2-100-250
  rect 1.397x1.778 hole 0.813: 1(-1.27,0)
  oval 1.397x1.778 hole 0.813: 2(1.27,0)
HEAD0202-RM
  rect 1.524x1.524 hole 1.143: 1(1.27,1.27)
  round 1.524 hole 1.143: 2(1.27,-1.27) 3(-1.27,1.27) 4(-1.27,-1.27)
HEAD0212-RM-SUB
  rect 1.524x1.524 hole 1.143: 1(13.97,1.27)
  round 1.524 hole 1.143: 2(13.97,-1.27) 3(11.43,1.27) 4(11.43,-1.27) 5(8.89,1.27) 6(8.89,-1.27) 7(6.35,1.27) 8(6.35,-1.27) 9(3.81,1.27) 10(3.81,-1.27) 11(1.27,1.27) 12(1.27,-1.27) 13(-1.27,1.27) 14(-1.27,-1.27) 15(-3.81,1.27) 16(-3.81,-1.27) 17(-6.35,1.27) 18(-6.35,-1.27) 19(-8.89,1.27) 20(-8.89,-1.27) 21(-11.43,1.27) 22(-11.43,-1.27) 23(-13.97,1.27) 24(-13.97,-1.27)
HOLE138-8STAR
  round 3.505 hole 3.505 unplated: (0,0)
  round 0.711 hole 0.305: 1(-3.131,0) 2(-2.214,-2.214) 3(0,-3.131) 4(2.214,-2.214) 5(3.131,0) 6(2.214,2.214) 7(0,3.131) 8(-2.214,2.214)
HSC0402
  rect 0.508x0.508 smd: 1(-0.406,0) 2(0.406,0)
HSC0402-TA
  rect 0.432x0.508 smd: 1(-0.368,0) 2(0.368,0)
HSL0402
  rect 0.635x0.508 smd: 1(-0.508,0) 2(0.508,0)
HSL0402-TC
  rect 0.457x0.508 smd: 1(-0.381,0) 2(0.381,0)
HSL1007
  rect 0.914x1.626 smd: 1(-1.1,0) 2(1.1,0)
HSOD323A
  rect 1.118x0.508 smd: 1(1.372,0) 2(-1.372,0)
HVQFN32
  oval 0.254x0.889 smd: 1(-1.75,-2.5) 2(-1.25,-2.5) 3(-0.75,-2.5) 4(-0.25,-2.5) 5(0.25,-2.5) 6(0.75,-2.5) 7(1.25,-2.5) 8(1.75,-2.5) 17(1.75,2.5) 18(1.25,2.5) 19(0.75,2.5) 20(0.25,2.5) 21(-0.25,2.5) 22(-0.75,2.5) 23(-1.25,2.5) 24(-1.75,2.5)
  oval 0.889x0.254 smd: 9(2.5,-1.75) 10(2.5,-1.25) 11(2.5,-0.75) 12(2.5,-0.25) 13(2.5,0.25) 14(2.5,0.75) 15(2.5,1.25) 16(2.5,1.75) 25(-2.5,1.75) 26(-2.5,1.25) 27(-2.5,0.75) 28(-2.5,0.25) 29(-2.5,-0.25) 30(-2.5,-0.75) 31(-2.5,-1.25) 32(-2.5,-1.75)
  rect 2.21x2.21 smd: 33(0,0)
ID-BOARD
  round 1.016 smd: 1(0,0)
JTDA18250
  oval 1.778x2.54 hole 1.016x1.778: 1(-11.17,-7.5) 2(-11.17,7.5)
  oval 1.778x5.08 hole 1.27x4.572: 3(-14.87,7.5) 4(-14.87,-7.5)
  oval 3.302x1.778 hole 2.54x1.016: 5(-9.25,-13.675) 6(9.25,-13.675) 7(9.25,13.675) 8(-9.25,13.675)
L6X6X4_5
  rect 1.651x5.715 smd: 1(-2.3,0) 2(2.3,0)
MLF24B-050-0404L
  rect 0.254x0.559 smd: 1(-1.25,-1.879) 2(-0.75,-1.879) 3(-0.25,-1.879) 4(0.25,-1.879) 5(0.75,-1.879) 6(1.25,-1.879) 13(1.25,1.879) 14(0.75,1.879) 15(0.25,1.879) 16(-0.25,1.879) 17(-0.75,1.879) 18(-1.25,1.879)
  rect 0.559x0.254 smd: 7(1.879,-1.25) 8(1.879,-0.75) 9(1.879,-0.25) 10(1.879,0.25) 11(1.879,0.75) 12(1.879,1.25) 19(-1.879,1.25) 20(-1.879,0.75) 21(-1.879,0.25) 22(-1.879,-0.25) 23(-1.879,-0.75) 24(-1.879,-1.25)
  rect 2.54x2.54 smd: 25(0,0)
MLF40B-040-0505L
  rect 0.203x0.559 smd: 1(-1.8,-2.379) 2(-1.4,-2.379) 3(-1,-2.379) 4(-0.6,-2.379) 5(-0.2,-2.379) 6(0.2,-2.379) 7(0.6,-2.379) 8(1,-2.379) 9(1.4,-2.379) 10(1.8,-2.379) 21(1.8,2.379) 22(1.4,2.379) 23(1,2.379) 24(0.6,2.379) 25(0.2,2.379) 26(-0.2,2.379) 27(-0.6,2.379) 28(-1,2.379) 29(-1.4,2.379) 30(-1.8,2.379)
  rect 0.559x0.203 smd: 11(2.379,-1.8) 12(2.379,-1.4) 13(2.379,-1) 14(2.379,-0.6) 15(2.379,-0.2) 16(2.379,0.2) 17(2.379,0.6) 18(2.379,1) 19(2.379,1.4) 20(2.379,1.8) 31(-2.379,1.8) 32(-2.379,1.4) 33(-2.379,1) 34(-2.379,0.6) 35(-2.379,0.2) 36(-2.379,-0.2) 37(-2.379,-0.6) 38(-2.379,-1) 39(-2.379,-1.4) 40(-2.379,-1.8)
  rect 3.175x3.175 smd: 41(0,0)
MLF48B-040-0606L
  rect 0.203x0.61 smd: 1(-2.2,-2.879) 2(-1.8,-2.879) 3(-1.4,-2.879) 4(-1,-2.879) 5(-0.6,-2.879) 6(-0.2,-2.879) 7(0.2,-2.879) 8(0.6,-2.879) 9(1,-2.879) 10(1.4,-2.879) 11(1.8,-2.879) 12(2.2,-2.879) 25(2.2,2.879) 26(1.8,2.879) 27(1.4,2.879) 28(1,2.879) 29(0.6,2.879) 30(0.2,2.879) 31(-0.2,2.879) 32(-0.6,2.879) 33(-1,2.879) 34(-1.4,2.879) 35(-1.8,2.879) 36(-2.2,2.879)
  rect 0.61x0.203 smd: 13(2.879,-2.2) 14(2.879,-1.8) 15(2.879,-1.4) 16(2.879,-1) 17(2.879,-0.6) 18(2.879,-0.2) 19(2.879,0.2) 20(2.879,0.6) 21(2.879,1) 22(2.879,1.4) 23(2.879,1.8) 24(2.879,2.2) 37(-2.879,2.2) 38(-2.879,1.8) 39(-2.879,1.4) 40(-2.879,1) 41(-2.879,0.6) 42(-2.879,0.2) 43(-2.879,-0.2) 44(-2.879,-0.6) 45(-2.879,-1) 46(-2.879,-1.4) 47(-2.879,-1.8) 48(-2.879,-2.2)
  rect 3.683x3.683 smd: 49(0,0)
MLF48G-040-0606L
  rect 0.203x0.61 smd: 1(-2.2,-2.903) 2(-1.8,-2.903) 3(-1.4,-2.903) 4(-1,-2.903) 5(-0.6,-2.903) 6(-0.2,-2.903) 7(0.2,-2.903) 8(0.6,-2.903) 9(1,-2.903) 10(1.4,-2.903) 11(1.8,-2.903) 12(2.2,-2.903) 25(2.2,2.903) 26(1.8,2.903) 27(1.4,2.903) 28(1,2.903) 29(0.6,2.903) 30(0.2,2.903) 31(-0.2,2.903) 32(-0.6,2.903) 33(-1,2.903) 34(-1.4,2.903) 35(-1.8,2.903) 36(-2.2,2.903)
  rect 0.61x0.203 smd: 13(2.903,-2.2) 14(2.903,-1.8) 15(2.903,-1.4) 16(2.903,-1) 17(2.903,-0.6) 18(2.903,-0.2) 19(2.903,0.2) 20(2.903,0.6) 21(2.903,1) 22(2.903,1.4) 23(2.903,1.8) 24(2.903,2.2) 37(-2.903,2.2) 38(-2.903,1.8) 39(-2.903,1.4) 40(-2.903,1) 41(-2.903,0.6) 42(-2.903,0.2) 43(-2.903,-0.2) 44(-2.903,-0.6) 45(-2.903,-1) 46(-2.903,-1.4) 47(-2.903,-1.8) 48(-2.903,-2.2)
  rect 4.064x4.064 smd: 49(0,0)
QFN28B-040-0404LH
  oval 0.203x0.889 smd: 1(-1.2,-1.975) 2(-0.8,-1.975) 3(-0.4,-1.975) 4(0,-1.975) 5(0.4,-1.975) 6(0.8,-1.975) 7(1.2,-1.975) 15(1.2,1.975) 16(0.8,1.975) 17(0.4,1.975) 18(0,1.975) 19(-0.4,1.975) 20(-0.8,1.975) 21(-1.2,1.975)
  oval 0.889x0.203 smd: 8(1.975,-1.2) 9(1.975,-0.8) 10(1.975,-0.4) 11(1.975,0) 12(1.975,0.4) 13(1.975,0.8) 14(1.975,1.2) 22(-1.975,1.2) 23(-1.975,0.8) 24(-1.975,0.4) 25(-1.975,0) 26(-1.975,-0.4) 27(-1.975,-0.8) 28(-1.975,-1.2)
  rect 2.057x2.057 smd: 29(0,0)
RF4-TDK-ATB2012E
  rect 0.762x0.356 smd: 1(-0.975,0.425) 2(-0.975,-0.425) 3(0.975,-0.425) 4(0.975,0.425)
SC0402
  rect 0.508x0.508 smd: 1(-0.406,0) 2(0.406,0)
SC0603
  rect 0.762x0.813 smd: 1(-0.699,0) 2(0.699,0)
SC0805
  rect 0.991x1.27 smd: 1(-0.813,0) 2(0.813,0)
SC1206
  rect 1.295x1.651 smd: 1(-1.346,0) 2(1.346,0)
SC1210
  rect 1.295x2.413 smd: 1(-1.346,0) 2(1.346,0)
SCAPC2-0606
  rect 3.302x1.397 smd: 1(-2.651,0) 2(2.651,0)
SD1714A
  rect 2.286x2.286 smd: 1(-2.286,0) 2(2.286,0)
SL0402
  rect 0.483x0.508 smd: 1(-0.394,0) 2(0.394,0)
SL0603
  rect 0.711x0.813 smd: 1(-0.74,0) 2(0.74,0)
SL0603A
  rect 0.889x1.016 smd: 1(-0.762,0) 2(0.762,0)
SL0805
  rect 0.94x1.27 smd: 1(-0.851,0) 2(0.851,0)
SOT23
  rect 1.016x1.27 smd: 1(-1.016,-1.143) 2(1.016,-1.143) 3(0,1.143)
SOT23-5
  rect 0.711x1.016 smd: 1(-0.95,-1.3) 2(0,-1.3) 3(0.95,-1.3) 4(0.95,1.3) 5(-0.95,1.3)
SOT223A
  rect 1.016x2.032 smd: 1(-2.286,-3.15) 2(0,-3.15) 3(2.286,-3.15)
  rect 3.302x2.032 smd: 4(0,3.15)
SR0402
  rect 0.508x0.508 smd: 1(-0.406,0) 2(0.406,0)
SR0603
  rect 0.711x0.813 smd: 1(-0.737,0) 2(0.737,0)
SR1206
  rect 1.295x1.6 smd: 1(-1.346,0) 2(1.346,0)
SRN8-0804
  rect 0.279x0.533 smd: 1(-0.762,-0.521) 2(-0.254,-0.521) 3(0.254,-0.521) 4(0.762,-0.521) 5(0.762,0.521) 6(0.254,0.521) 7(-0.254,0.521) 8(-0.762,0.521)
SWPA4020S
  rect 1.905x3.683 smd: 1(-1.55,0) 2(1.55,0)
SX2-1205
  rect 4.826x1.524 smd: 1(-4.85,0) 2(4.85,0)
TO-252
  rect 1.27x2.032 smd: 1(-2.285,-3.375) 2(0,-3.375) 3(2.285,-3.375)
  rect 5.715x5.842 smd: 4(0,3.375)
TSSOP16EP
  rect 0.356x1.651 smd: 1(-2.275,-2.9) 2(-1.625,-2.9) 3(-0.975,-2.9) 4(-0.325,-2.9) 5(0.325,-2.9) 6(0.975,-2.9) 7(1.625,-2.9) 8(2.275,-2.9) 9(2.275,2.9) 10(1.625,2.9) 11(0.975,2.9) 12(0.325,2.9) 13(-0.325,2.9) 14(-0.975,2.9) 15(-1.625,2.9) 16(-2.275,2.9)
  rect 4.191x3.302 smd: 17(0,0)
unnamed
  round 0.813 hole 0.813 unplated: (-2.6,1.1) (-2.6,-1.1) (-1.3,1.1) (-1.3,-1.1) (0,1.1) (0,-1.1) (1.3,1.1) (1.3,-1.1) (2.6,1.1) (2.6,-1.1)
unnamed#2
  round 0.61 hole 0.61 unplated: (-2.2,1.1) (-1.1,1.1) (0,1.1) (1.1,1.1) (2.2,1.1)
XTAL2-200A
  round 2.286 hole 0.813: 1(-2.54,0) 2(2.54,0)

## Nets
1V1_ADC_T: C275.1 C309.1 LB23.2 U25.28 U25.33
1V1_AVDDREF: C254.1 R201.2 U25.31
1V1_VDD_T: C256.1 C273.1 C274.1 C276.1 C277.1 R223.2 U25.1 U25.12 U25.18 U25.21 U25.27 U25.37 U25.44
1V2_ADC_C: C18.1 C26.1 C43.1 LB5.1 U5.14 U5.15
1V2_ADC_S: C125.1 C209.1 LB13.2 U2.33
1V2_APLL_S: C126.1 C210.1 LB15.2 U2.28
1V2_DVDD_C: C15.1 C16.1 C17.1 C23.1 C67.1 R29.2 U5.4 U5.23 U5.35
1V2_DVDD_S: C109.1 C110.1 C113.1 C117.1 C205.1 LB10.2 U2.7 U2.17 U2.25 U2.42
1V8_T: C247.1 C278.1 C284.2 C293.2 LB2.2 R50.2 U20.4 U20.21 U21.2(TP-2) U21.4(TP-4)
3V3_AVDD_C: C24.1 C42.1 LB4.2 U5.17
3V3_AVDD_S: C86.1 C201.1 LB6.2 R69.1 U2.30
3V3_AVDD_T: C263.1 C311.1 R216.1 R221.2 U25.30
3V3_C: C5.1(TP-1) C12.1 C13.1 C14.1 C33.1 C45.1 C46.1 C47.1 C60.1 L6.2 R42.2 R45.2 R46.2 U1.2(TP-2) U1.4(TP-4) U4.7 U4.28 U4.32
3V3_DVDD_C: C20.1 C21.1 C22.1 C25.1 C68.1 R22.1 R23.1 R28.2 R37.1 U5.1 U5.24 U5.33
3V3_DVDD_S: C73.1 C74.1 C75.1 C81.1 C200.1 LB1.2 R35.1 R65.1 R66.1 R103.2 R104.1 R108.1 R116.2 U2.4 U2.11 U2.19 U2.45
3V3_DVDD_T: C156.1 C261.1 C262.1 C269.1 C272.1 LB19.2 R206.1 R207.1 U25.7 U25.17 U25.20 U25.25 U25.41 U25.45
3V3_MOS_C: C10.1 C36.1 C54.1 J7.5 L6.1 LB4.1 R28.1 U3.3(TP-3)
3V3_MOS_S: C7.1 C87.1 C88.1 J3.5 L21.1 LB1.1 LB6.1
3V3_MOS_T: C249.1 C265.1 C292.1 C312.1 C349.1 J4.5 LB16.1 LB19.1 R221.1 U18.1 U18.3 U21.3(TP-3)
3V3_RF: C57.1(TP-1) C144.1 C169.2 C195.2 C296.1 L21.2 R112.2 U14.2(TP-2) U14.4(TP-4) U34.23 U34.28
3V3_TUNER: C259.1 C260.1 C280.2 C286.1 C291.1 C328.1 LB16.2 R211.1 R213.1 R225.1 U20.11 U20.15 U20.22
5V0_MOS_C: C11.1 J7.3 LB3.2
5V0_MOS_S: C8.1 C92.1 C202.1 J3.3 LB47.1 U12.3
5V0_MOS_T: C301.1 C352.1 J4.3 Q12.2 R200.1
12V0_MOS_S: C9.1 C136.1 C183.1 J3.1 L7.1 R117.1 R121.1 U17.3
GND: C1.2 C4.2 C5.2(TP-2) C7.2 C8.2 C9.2 C10.2 C11.2 C12.2 C13.2 C14.2 C15.2 C16.2 C17.2 C18.2 C19.2 C20.2 C21.2 C22.2 C23.2 C24.2 C25.2 C26.2 C30.1 C31.2 C32.2 C33.2 C34.2 C36.2 C37.2 C38.2 C41.2 C42.2 C43.2 C44.2 C45.2 C46.2 C47.2 C50.2 C51.2 C53.2 C54.2 C55.2 C57.2(TP-2) C58.2 C59.1 C60.2 C61.2 C62.2 C63.2 C67.2 C68.2 C71.1 C72.2 C73.2 C74.2 C75.2 C76.2 C77.2 C78.2 C81.2 C82.2 C83.2 C84.2 C86.2 C87.2 C88.2 C92.2 C103.2 C104.2 C105.2 C109.2 C110.2 C113.2 C117.2 C125.2 C126.2 C130.2 C131.2 C134.2 C136.2 C144.2 C145.2 C148.2 C151.2 C156.2 C163.1 C166.2 C167.2 C168.1 C169.1 C170.2 C171.1 C172.2 C174.2 C176.2 C183.2 C190.2 C194.2 C195.1 C200.2 C201.2 C202.2 C204.2 C205.2 C209.2 C210.2 C217.2 C221.2 C224.2 C225.1 C226.2 C241.2 C244.2 C246.2 C247.2 C249.2 C252.2 C253.2 C254.2 C256.2 C259.2 C260.2 C261.2 C262.2 C263.2 C265.2 C268.2 C269.2 C272.2 C273.2 C274.2 C275.2 C276.2 C277.2 C278.2 C279.2 C280.1 C284.1 C285.2 C286.2 C287.2 C288.2 C290.2 C291.2 C292.2 C293.1 C294.1 C295.2 C296.2 C298.2 C299.2 C300.2 C301.2 C302.2 C304.1 C305.1 C309.2 C311.2 C312.2 C322.1 C325.1 C326.2 C327.2 C328.2 C340.2 C346.1 C349.2 C352.2 C414.2 C487.1 C531.2 C532.2 C534.2 C535.2 C536.2 C537.2 C538.2 C545.2 D1.1 D1.2 D2.1 D2.2 D3.1 D3.2 D4.1 D4.2 D11.1 J1.3 J1.4 J1.5 J1.6 J1.7 J1.8 J2.3 J2.4 J2.5 J2.6 J2.7 J2.8 J3.2 J3.4 J3.6 J3.7 J3.8 J3.18 J3.20 J4.2 J4.4 J4.6 J4.7 J4.8 J4.18 J4.20 J5.1 J5.2 J5.3 J5.4 J6.1 J6.2 J6.3 J6.4 J7.2 J7.4 J7.6 J7.7 J7.8 J7.18 J7.20 J15.1 J15.2 J15.3 J15.4 J16.3 J16.4 J16.5 J16.6 J16.7 J16.8 L2.2 L3.2 L4.2 L5.2 L8.2 L12.2 L15.2 L16.1 L17.2 M1.1 M1.2 M1.3 M1.4 M1.5 M1.6 M1.7 M1.8 M2.1 M2.2 M2.3 M2.4 M2.5 M2.6 M2.7 M2.8 M3.1 M3.2 M3.3 M3.4 M3.5 M3.6 M3.7 M3.8 M4.1 M4.2 M4.3 M4.4 M4.5 M4.6 M4.7 M4.8 M5.1 M5.2 M5.3 M5.4 M5.5 M5.6 M5.7 M5.8 M6.1 M6.2 M6.3 M6.4 M6.5 M6.6 M6.7 M6.8 M7.1 M7.2 M7.3 M7.4 M7.5 M7.6 M7.7 M7.8 M8.1 M8.2 M8.3 M8.4 M8.5 M8.6 M8.7 M8.8 M9.1 M9.2 M9.3 M9.4 M9.5 M9.6 M9.7 M9.8 M10.1 M10.2 M10.3 M10.4 M10.5 M10.6 M10.7 M10.8 M11.1 M11.2 M11.3 M11.4 M11.5 M11.6 M11.7 M11.8 M12.1 M12.2 M12.3 M12.4 M12.5 M12.6 M12.7 M12.8 Q6.2 Q10.2 R1.2 R2.2 R3.2 R4.2 R18.2 R32.2 R41.2 R59.2 R64.2 R72.2 R83.2 R92.2 R102.1 R123.2 R141.2 R150.1 R157.1 R162.1 R171.2 R192.2 R197.2 R198.2 R204.2 R205.2 R208.2 R209.2 U2.29 U2.34 U2.47 U2.49 U4.1 U4.5 U4.11 U4.16 U4.18 U4.22 U4.29 U4.33 U5.6 U5.8 U5.9 U5.10 U5.11 U5.16 U5.18 U5.41 U17.1 U17.16 U17.17 U18.2 U20.14 U20.25 U25.29 U25.34 U25.49 U34.29
VINNQ: C267.1 C299.1 U25.36
VINPQ: C266.1 C300.1 U25.35
3130_AGC: R43.2 U5.7
3130_I2C_SCL: J7.23 R8.1
3130_I2C_SDA: J7.24 R9.1
3130_RSTN: J7.10 R30.1
3130_TSI_CLK: C71.2 J7.19 RN1.6
3130_TSI_D0: J7.17 RN3.8
3130_TSI_D1: J7.15 RN3.7
3130_TSI_D2: J7.16 RN3.6
3130_TSI_D3: J7.13 RN3.5
3130_TSI_D4: J7.14 RN2.7
3130_TSI_D5: J7.11 RN2.6
3130_TSI_D6: J7.12 RN2.5
3130_TSI_D7: J7.9 RN1.8
3130_TSI_SYNC: J7.22 RN1.5
3130_TSI_VALID: J7.21 RN1.7
3136_ADDR0: R41.1 U2.39
3136_ADDR1: R103.1 U2.38
3136_DISEQC_IN: Q6.3 R51.1 R116.1 U2.13
3136_DISEQC_OUT: R123.1 U2.12 U17.9
3136_FUNC_SEL: R4.1 U2.14
3136_HV_SEL: U2.18 U17.8
3136_I2C_SCL: C221.1 J3.23 R108.2 U2.41
3136_I2C_SDA: C217.1 J3.24 R104.2 U2.40
3136_IOUT_N: C307.2 U2.32
3136_IOUT_P: C303.2 U2.31
3136_LNB_EN: U2.21 U17.5
3136_QOUT_N: C186.2 U2.35
3136_QOUT_P: C306.2 U2.36
3136_RF_AGC: C37.1 R60.1 R127.2
3136_RSTN: C38.1 J3.10 R83.1 U2.15
3136_TS_CLK: R10.2 U2.46
3136_TS_OUT0: R13.2 U2.48
3136_TS_OUT1: R12.2 U2.1
3136_TS_OUT2: R14.2 U2.2
3136_TS_OUT3: R16.2 U2.3
3136_TS_OUT4: R19.2 U2.5
3136_TS_OUT5: R20.2 U2.6
3136_TS_OUT6: R21.2 U2.8
3136_TS_OUT7: R25.2 U2.9
3136_TS_SYNC: R226.2 U2.43
3136_TS_VAL: C176.1 R5.2 U2.44
3136_TSI_CLK: J3.19 R10.1
3136_TSI_D0: J3.17 R13.1
3136_TSI_D1: J3.15 R12.1
3136_TSI_D2: J3.16 R14.1
3136_TSI_D3: J3.13 R16.1
3136_TSI_D4: J3.14 R19.1
3136_TSI_D5: J3.11 R20.1
3136_TSI_D6: J3.12 R21.1
3136_TSI_D7: J3.9 R25.1
3136_TSI_SYNC: J3.22 R226.1
3136_TSI_VALID: J3.21 R5.1
3136_XIN: C172.1 R24.1 U2.23 X6.2(TP-2)
3136_XOUT: C174.1 R24.2 U2.22 X6.1(TP-1)
3137_ADDR0: R209.1 U25.40
3137_ADDR1: R208.1 U25.38
3137_FUNC_SEL: R205.1 U25.14
3137_I2C_SCL: J4.23 R81.1 R206.2
3137_I2C_SDA: J4.24 R80.1 R207.2
3137_IF_AGC: C268.1 R196.1 R199.2
3137_RSTN: C340.1 J4.10 R198.1 U25.15
3137_TSI_CLK: J4.19 R133.1
3137_TSI_D0: J4.17 R134.1
3137_TSI_D1: J4.15 R165.1
3137_TSI_D2: J4.16 R227.1
3137_TSI_D3: J4.13 R228.1
3137_TSI_D4: J4.14 R230.1
3137_TSI_D5: J4.11 R231.1
3137_TSI_D6: J4.12 R232.1
3137_TSI_D7: J4.9 R233.1
3137_TSI_SYNC: J4.22 R128.1
3137_TSI_VALID: J4.21 R132.1
3137_XIN: C325.2 R47.1 R164.2 U25.23 X3.2(TP-2)
3137_XOUT: C322.2 R164.1 U25.22 X3.1(TP-1)
18250B_SCL_T: R27.2 R39.2 R45.1
18250B_SDA_T: R26.2 R40.2 R46.1
AC2012_SCL_T: R61.2 R65.2 U2.27
AC2012_SDA_T: R62.2 R66.2 U2.26
ANT_CTRL/LOCK: R150.2 R224.2 U25.16
ANT_POWER: C279.1 L13.2 Q11.3 R157.2
CLK_TU_OUT: C330.2 R47.2
DEMO_VIN: C50.1 R7.2 U5.12
DEMO_VIP: C51.1 R11.2 U5.13
I2C_SCL_3130: C84.1 R8.2 R23.2 U5.20
I2C_SDA_3130: C72.1 R9.2 R22.2 U5.19
IF_OUTN: C266.2 C335.2
IF_OUTP: C267.2 C337.2
LNB_PWR: C58.1 C64.1 C78.1 C104.1 C155.2 C170.1 D17.2 D27.1 J16.2
LNB_PWR_B: C166.1 C287.1 C288.1 D27.2 R166.2
LOOPTHROUGH: C283.1 J16.1 R166.1
LT: C66.2 U4.3
MXL603_SCL: R143.2 R213.2 U25.26
MXL603_SDA: R137.2 R211.2 U25.24
REG2OUT: C130.1 C131.1 C225.2 C414.1 U34.1 U34.2 U34.5 U34.10 U34.25
RESET_TUNER: C302.1 R225.2 U20.10 U25.19
RF_IN_18250B: C56.1 J1.2
RF_IN_T: C331.1 J2.2 L13.1
RF_OUT_18250B: C79.1 J1.1
RF_OUT_T: C333.1 J2.1
RFIN: C65.2 U4.2
TS_RSTN_DEMO: C53.1 R30.2 R37.2 U5.37
$3N275: R69.2 R127.1 U2.37
$3N304: C226.1 U2.24
$3N444: C103.1 C204.1 LB10.1 LB13.1 LB15.1 R68.2 U12.2 U12.4
$3N446: R68.1 R141.1 U12.1
$4N322: C487.2 U34.26 U34.27
$4N324: C168.2 U34.24
$4N325: C190.1 C194.1 U34.20 U34.21 U34.22
$4N326: C538.1 R61.1 U34.15
$4N327: C534.1 R62.1 U34.16
$4N328: R72.1 U34.17
$4N329: C532.1 U34.18 X4.1(TP-1)
$4N330: C531.1 U34.19 X4.2(TP-2)
$4N331: R59.1 U34.14
$4N332: R64.1 U34.13
$4N333: C303.1 C537.1 U34.12
$4N334: C241.1 C307.1 U34.11
$4N336: C186.1 C535.1 U34.9
$4N337: C306.1 C536.1 U34.8
$4N338: L1.2 R63.1 U34.3
$4N360: C304.2 R63.2
$4N368: C64.2 C305.2 L1.1
$4N406: C148.1 U34.4
$4N416: C545.1 R60.2 U34.6
$4N439: R2.1 R112.1 U14.1(TP-1)
$4N597: C282.1 C283.2 L16.2
$4N600: C282.2 U34.7
$4N629: C105.1 C145.1 LB47.2 U14.3(TP-3)
$4N809: C171.2 U17.2
$4N822: C163.2 C175.2 U17.4
$4N827: C175.1 R102.2
$4N836: R117.2 U17.6
$4N838: R121.2 U17.7
$4N844: D7.1 L7.2 U17.15
$4N849: C139.1 U17.14
$4N851: C1.1 C139.2 D8.2 L9.2 U17.13
$4N859: C134.1 D7.2 L9.1
$4N880: C151.1 C167.1 C244.1 D8.1 D11.2 D17.1 U17.12
$4N898: R92.1 U17.11
$4N900: C246.1 U17.10
$4N922: Q6.1 R51.2 R114.1
$4N925: C155.1 R35.2 R114.2
$5N739: R18.1 R50.1 U21.1(TP-1)
$5N778: R199.1 R216.2 U25.39
$5N783: R132.2 U25.47
$5N784: R133.2 U25.48
$5N786: R128.2 U25.46
$5N788: C298.1 R81.2 U25.43
$5N863: R134.2 U25.2
$5N867: R204.1 U25.32
$5N880: C345.2 R79.2 R197.1 U18.4
$5N881: C224.1 C345.1 LB23.1 R79.1 R222.1 R223.1 U18.5
$5N882: R201.1 R222.2
$5N900: C295.1 R80.2 U25.42
$5N935: R165.2 U25.3
$5N944: R227.2 U25.4
$5N946: R228.2 U25.5
$5N948: R230.2 U25.6
$5N950: R231.2 U25.8
$5N952: R232.2 U25.9
$5N954: R233.2 U25.10
$6N450: Q12.1 R162.2 R217.1
$6N451: Q11.2 R200.2 R217.2
$6N454: C252.1 R137.1 U20.17
$6N455: C253.1 R143.1 U20.16
$6N457: C326.1 U20.19 X5.2(TP-2)
$6N458: C338.1 L10.2 L11.1 R167.2 R169.1
$6N459: L11.2 L14.1 R169.2
$6N460: C331.2 C332.1 D1.3
$6N461: C338.2 L12.1
$6N463: Q11.1 R214.2
$6N464: Q10.1 R224.1
$6N465: C329.2 R170.1
$6N466: C294.2 U20.23
$6N467: C330.1 U20.18
$6N468: C285.1 R196.2 U20.6
$6N470: C318.2 U20.2
$6N471: C321.2 U20.3
$6N487: C332.2 L10.1 R167.1
$6N488: C329.1 C333.2 D2.3
$6N491: R170.2 U20.24
$6N492: C327.1 U20.20 X5.1(TP-1)
$6N503: Q10.3 Q12.3 R214.1
$6N504: C337.1 U20.7
$6N505: C335.1 U20.8
$6N513: R192.1 U20.9
$6N515: C290.1 LB2.1 U20.12
$6N592: C346.2 L14.2 Z1.3
$6N593: C321.1 R195.1 Z1.2
$6N594: R171.1 Z1.4
$6N595: C318.1 R195.2 Z1.1
$7N202: R17.1 R32.1 U3.1(TP-1)
$7N218: R26.1 U5.3
$7N219: R27.1 U5.2
$7N227: RN1.3 U5.25
$7N228: RN1.4 U5.22
$7N237: C19.1 C55.1 LB5.2 R3.1 R17.2 R29.1 U3.2(TP-2) U3.4(TP-4)
$7N362: R6.1 R31.2 U5.40
$7N366: C62.1 R31.1 U5.39 X1.2
$7N370: C63.1 R6.2 X1.1
$7N391: RN2.2 U5.30
$7N393: RN2.3 U5.29
$7N395: RN2.4 U5.28
$7N397: RN1.1 U5.27
$7N399: RN1.2 U5.26
$7N402: RN3.4 U5.31
$7N404: RN3.3 U5.32
$7N406: RN3.2 U5.34
$7N408: RN3.1 U5.36
$8N5: C6.1 C40.1 C48.2 R15.1 R34.2
$8N73: C40.2 C65.1 D3.3 R15.2
$8N179: R1.1 R42.1 U1.1(TP-1)
$8N211: C30.2 U4.30
$8N230: C31.1 R33.1 U4.26
$8N237: C32.1 R33.2 R43.1
$8N249: C35.1 U4.24
$8N251: C39.1 U4.23
$8N253: C35.2 C59.2 R7.1
$8N255: C39.2 C61.1 R11.1
$8N297: C82.1 R39.1 U4.21
$8N299: C83.1 R40.1 U4.20
$8N324: C2.1 C69.1 U4.12
$8N326: C2.2 C70.1 U4.13
$8N328: C69.2 X2.1(TP-1)
$8N330: C70.2 X2.2(TP-2)
$8N351: C76.1 R38.1 R44.1 U4.9
$8N354: C44.1 R38.2
$8N359: C77.1 R44.2 U4.10
$8N375: C41.1 U4.8
$8N396: C6.2 L2.1
$8N403: C3.2 C48.1 C85.1 R34.1 R36.2
$8N409: C85.2 L3.1
$8N416: C3.1 C28.1 C49.2 R36.1
$8N419: C28.2 L15.1
$8N429: C29.1 C49.1 C52.2
$8N432: C29.2 L17.1
$8N437: C27.2 L4.1
$8N439: C27.1 C52.1 C80.2
$8N444: C56.2 C80.1 L5.1
$8N472: C66.1 C79.2 D4.3 L8.1
$8N485: C4.1 C34.1 LB3.1 U1.3(TP-3)

Pads without a net: ID1 1; ID2 1; ID3 1; ID4 1; ID5 1; ID6 1; J4 1; J7 1; RN2 1 8; U2 10 16 20; U4 4 6 14 15 17 19 25 27 31; U5 5 21 38; U20 1 5 13; U25 11 13

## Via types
v1: diameter 0.559, hole 0.254, TOP to BOTTOM, 3912 vias

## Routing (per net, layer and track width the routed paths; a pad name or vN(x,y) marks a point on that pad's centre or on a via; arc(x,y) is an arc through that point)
1V1_ADC_T: length 35
  TOP w0.203: U25.33 22.53,40.86 v1(22.4,40.99) ; U25.28 24.53,41.18
  TOP w0.381: LB23.2 42.58,46.83 v1(42.46,46.96) ; 24.53,41.18 24.68,41.32 24.68,42.11 C275.1 v1(26.33,43)
  BOTTOM w0.381: C309.1 22.52,40.87 v1(22.4,40.99) 22.4,42.27 23.13,43 v1(26.33,43) 27.83,44.49 27.83,46.04 32.3,50.51 40.43,50.51 42.46,48.48 v1(42.46,46.96)
1V1_AVDDREF: length 3.3
  TOP w0.203: v1(23.51,41.07) 23.33,40.89 U25.31
  BOTTOM w0.607: R201.2 23.51,42.16 v1(23.51,41.07) 23.51,40.15 C254.1
1V1_VDD_T: length 15
  TOP w0.203: U25.27 24.93,40.74 25.19,40.99 ; v1(27.62,34.28) 27.37,34.54 25.87,34.54 25.73,34.4 U25.12 ; v1(28.77,38.55) 28.74,38.55 28.59,38.7 27.62,38.7 27.1,38.18 U25.21 ; U25.18 27.34,36.98 27.56,36.76 v1(28.75,36.76) ; U25.1 21.33,34.07 20.71,33.45 v1(19.72,33.45) ; v1(20.33,39.89) 20.16,39.71 20.16,39.58 20.36,39.38 U25.37 ; U25.44 19.43,36.58 18.78,35.93 v1(18.78,35.82)
  TOP w0.381: v1(26.71,41.12) 25.31,41.12 25.19,40.99
  vias: v1(39.16,46.96) v1(40.04,46.96)
1V2_ADC_C: length 14.5
  TOP w0.203: U5.14 90.88,39.49 91.04,39.65 ; U5.15 90.48,40.01
  TOP w0.305: 89.77,42.82 89.16,42.21 89.16,41.05 89.7,40.52 C26.1 89.97,40.52 90.48,40.01 ; 89.77,42.95 89.8,42.95 90.66,42.09 90.66,41.08 91.22,40.52 C18.1 91.42,40.04 91.04,39.65
  TOP w0.508: 89.77,42.82 C43.1 LB5.1
1V2_ADC_S: length 30.7
  TOP w0.203: U2.33 140.17,40.96 v1(140.03,41.1)
  TOP w0.381: v1(130.79,23.11) C209.1 LB13.2
  BOTTOM w0.381: v1(140.03,41.1) 139.94,41.19 C125.1 138.65,41.19 138.27,41.57 133.28,41.57 132.44,40.73 132.44,28.92 129.62,26.1 129.62,24.28 v1(130.79,23.11)
1V2_APLL_S: length 38.2
  TOP w0.203: v1(141.93,41.25) 142.17,41.01 U2.28
  TOP w0.381: LB15.2 C210.1 v1(130.79,21.33)
  BOTTOM w0.381: v1(141.93,41.25) 141.9,41.22 C126.1 141.18,41.84 140.43,42.59 139.81,42.59 139.56,42.84 132.7,42.84 131.05,41.19 131.05,29.36 128.35,26.66 128.35,23.77 v1(130.79,21.33)
1V2_DVDD_C: length 26.3
  TOP w0.203: U5.4 93.62,35.07 v1(93.67,35.02) ; v1(89.97,32.18) 90.08,32.29 U5.35 ; U5.23 87.37,36.67 87.21,36.84 v1(86.85,36.84)
  TOP w0.305: C17.1 94.2,35.18 94.04,35.02 v1(93.67,35.02) ; C23.1 86.82,36.86 v1(86.85,36.84)
  TOP w0.381: C16.1 89.95,31.6 89.95,32.16 v1(89.97,32.18)
  TOP w0.508: v1(86.98,41.22) 86.98,41.56 87.95,42.54 C15.1 87.95,43.98 C67.1 88.17,45.64 R29.2
  BOTTOM w0.254: v1(89.97,32.18) 89.97,34.04
  BOTTOM w0.381: v1(86.85,36.84) 87.45,36.84 88.49,35.8 88.49,34.44 88.88,34.04 92.69,34.04 v1(93.67,35.02)
  BOTTOM w0.508: v1(86.98,41.22) 86.85,41.09 v1(86.85,36.84)
1V2_DVDD_S: length 5.4
  TOP w0.152: U2.42 137.03,37.64 v1(137.01,37.67)
  TOP w0.203: U2.17 144.82,36.84 v1(144.98,36.68) ; U2.7 141.37,33.44 v1(141.41,33.4) ; U2.25 143.37,41.04 v1(143.58,41.25)
  BOTTOM w0.381: C117.1 v1(144.98,36.68)
  vias: v1(130.72,25.04) v1(131.48,25.06)
1V8_T: length 102.6
  TOP w0.254: U20.21 30.12,60.42 30.39,60.7 31.03,60.7 ; U20.4 26.97,63.21 26.58,63.59 25.69,63.59 25.34,63.95 C293.2
  TOP w0.381: LB2.2 v1(22.92,55.59) ; C284.2 31.03,60.7 ; C293.2 v1(25.34,65.12)
  TOP w0.508: R50.2 40.04,28.44 40.4,28.8 U21.2 ; v1(34.11,52.01) 34.11,52 35.09,51.02 40.55,51.02 41.31,51.78 v1(41.44,51.78) 41.44,52.55 42.2,53.31 42.2,68.38 40.58,70.01 37.82,70.01 33.39,65.58 33.39,61.74 32.35,60.7 C284.2 ; v1(43.4,51.78) 49.19,51.78 50.18,50.79 50.18,34.31 C278.1
  BOTTOM w0.508: v1(25.34,65.12) 24.17,65.12 22.42,63.37 22.42,56.1 v1(22.92,55.59) 25.84,52.68 33.45,52.68 v1(34.11,52.01) ; v1(43.4,51.78) v1(41.44,51.78)
3V3_AVDD_C: length 8.4
  TOP w0.203: 89.12,39.77 89.68,39.21 U5.17
  TOP w0.305: C42.1 85.41,41.6 86.49,40.52 C24.1 89.12,39.77
  TOP w0.381: C42.1 85.41,42.3 LB4.2
3V3_AVDD_S: length 12.8
  TOP w0.203: 141.37,41.13 U2.30
  TOP w0.254: 141.37,41.13 141.37,41.73 142.27,42.63 v1(142.27,43.16)
  TOP w0.381: R69.1 136.81,43.81 137.36,44.35 v1(137.58,44.35)
  BOTTOM w0.508: LB6.2 134.4,44.35 C201.1 v1(137.58,44.35) 141.4,44.35 C86.1 141.77,43.67 v1(142.27,43.16)
3V3_AVDD_T: length 18.3
  TOP w0.203: 24.04,41.42 24.04,40.84 23.73,40.53 U25.30
  TOP w0.381: 24.04,41.42 24.04,42.89 C263.1
  TOP w0.508: v1(24.85,44.29) 24.85,43.33 24.52,43 C263.1 ; v1(16.04,43.27) R216.1 17.41,42.82 C311.1 R221.2
  BOTTOM w0.508: v1(24.85,44.29) 24.73,44.42 17.18,44.42 v1(16.04,43.27)
3V3_C: length 51.4
  TOP w0.254: U4.7 86.77,66.14 86.47,66.44 v1(86.47,66.42) ; v1(91.45,64.74) U4.32 ; U4.28 91.42,62.74
  TOP w0.381: C33.1 C5.1 86.7,66.64 v1(86.47,66.42) ; 92.43,61.51 C46.1 92.43,61.98 92.21,62.2 92.21,62.66 C12.1 91.42,62.74 ; R42.2 105.73,36.09 ; v1(91.45,64.74) 92.16,64.74 92.21,64.69 ; R46.2 v1(84.18,55.87) ; v1(86.77,55.88) R45.2
  TOP w0.508: 92.43,61.51 92.43,61.12 92.9,60.65 95.36,60.65 ; 95.36,65.42 94.85,65.93 92.64,65.93 92.21,65.5 C45.1 92.21,64.69
  TOP w0.762: 95.36,65.42 C47.1 v1(95.36,55.87) 95.36,51.9 97.71,49.55
  BOTTOM w0.508: v1(86.47,66.42) 88.15,64.74 v1(91.45,64.74) ; v1(95.36,55.87) 95.35,55.88 v1(86.77,55.88) 86.11,55.88 86.11,55.87 v1(84.18,55.87)
3V3_DVDD_C: length 47
  TOP w0.203: v1(93.53,33.51) 93.17,33.87 93.17,33.87 U5.1 ; v1(86.85,36.12) 87,36.27 U5.24 ; U5.33 89.28,32.82 88.93,32.47 v1(88.93,32.26)
  TOP w0.305: v1(86.85,36.12) 86.57,35.84 C21.1
  TOP w0.381: R37.1 82.96,25.7 v1(82.05,25.7) ; C20.1 88.63,31.96 v1(88.93,32.26) ; C22.1 93.69,33.35 v1(93.53,33.51) ; R23.1 v1(82.05,38.23) ; R22.1 v1(82.05,40.95)
  TOP w0.508: v1(87.61,33.07) 87.15,32.6 87.15,32.58 85.73,31.17 v1(82.05,31.17) ; R28.2 82.06,23.65 C68.1 82.05,24.9 C25.1 82.04,25.69 v1(82.05,25.7)
  BOTTOM w0.381: 88.35,33.81 87.95,34.21 87.95,35.45 87.28,36.12 v1(86.85,36.12) ; 88.35,33.81 88.93,33.23 v1(88.93,32.26) 89.68,31.51 90.19,31.51 90.62,31.95 90.62,33.24 90.89,33.51 v1(93.53,33.51) ; 88.35,33.81 v1(87.61,33.07) ; v1(82.05,40.95) v1(82.05,38.23) v1(82.05,31.17)
  BOTTOM w0.508: v1(82.05,31.17) v1(82.05,25.7)
3V3_DVDD_S: length 66.3
  TOP w0.203: v1(143.45,33.38) 142.97,33.86 U2.11 ; U2.19 145.31,37.64 v1(145.49,37.82) ; U2.4 140.17,34.56 140.17,33.93 139.9,33.66 139.9,33.4 139.88,33.38 v1(139.89,33.38) ; U2.45 137.25,36.44 v1(137.11,36.3)
  TOP w0.381: LB1.2 v1(147.3,29.58) ; R65.1 142.02,44.04 142.02,45.33 v1(142.12,45.43) ; v1(148.05,47.86) 149.44,49.25 153.46,49.25 154.51,48.2 v1(154.51,40.76) ; v1(166.32,42.79) 166.78,42.79 167.11,43.13 R35.1 ; v1(133.94,38) 134.19,37.76 R108.1 ; v1(144.53,45.43) 144.24,45.14 R66.1 ; R104.1 v1(133.97,39.77) ; R116.2 v1(164.52,41.27)
  BOTTOM w0.381: v1(142.12,45.43) v1(144.53,45.43) 146.96,47.86 v1(148.05,47.86) ; v1(147.3,29.58) 150.6,32.89 153.12,32.89 154.51,34.27 v1(154.51,40.76) 154.51,40.76 164.02,40.76 v1(164.52,41.27) 166.05,42.79 v1(166.32,42.79)
  vias: v1(144.18,32.48) v1(144.94,32.48)
3V3_DVDD_T: length 12.5
  TOP w0.203: U25.25 v1(26.7,40.08) ; v1(19.59,37.78) U25.41 ; v1(27.83,36.2) 27.58,36.2 27.21,36.58 U25.17 ; U25.7 23.73,33.44 v1(23.57,33.27) ; U25.45 19.87,36.18 v1(19.5,35.81) ; v1(27.75,38.07) 27.46,37.78 U25.20
  TOP w0.381: v1(16.98,38.19) 18.58,38.19 19,37.78 v1(19.59,37.78)
  BOTTOM w0.381: R206.1 16.91,35.9 R207.1 16.91,38.13 v1(16.98,38.19)
  vias: v1(25.85,33.34) v1(26.46,33.83)
3V3_MOS_C: length 6.7
  TOP w0.381: LB4.1 80.87,43.78 80.12,44.53 77.77,44.53
  vias: v1(69.67,31.29) v1(70.45,31.26) v1(76.98,41.68) v1(77,40.92)
3V3_MOS_S:
  vias: v1(127.8,30.8) v1(127.77,29.89) v1(162.9,47.69) v1(162.9,46.93)
